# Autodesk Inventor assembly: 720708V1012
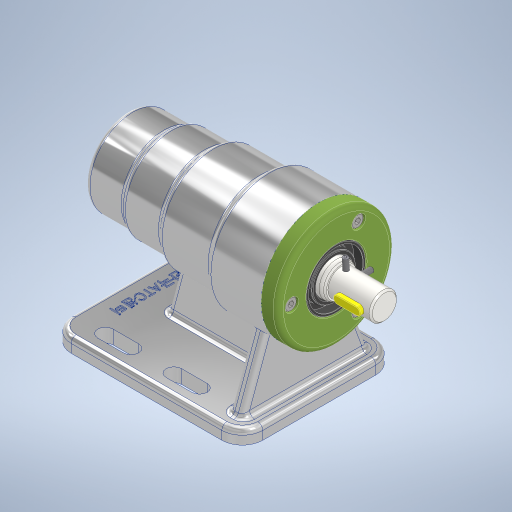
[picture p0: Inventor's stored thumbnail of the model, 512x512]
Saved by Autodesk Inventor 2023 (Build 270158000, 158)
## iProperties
Created: 2022-07
Part Number: 720708V1012
Document SubType Name: Assembly
Designer: owner
Author: owner
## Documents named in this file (12)
- C:\Users\owner\Desktop\720708V1012\720708V1012.iam
- C:\Users\owner\Desktop\720708V1012\본체.ipt
- C:\Users\owner\Desktop\720708V1012\V벨트풀리.ipt
- C:\Users\owner\Desktop\720708V1012\멈춤나사 M3.ipt
- C:\Users\owner\Desktop\720708V1012\베어링 6004.ipt
- C:\Users\owner\Desktop\720708V1012\베어링 51202.ipt
- C:\Users\owner\Desktop\720708V1012\볼트 M4.ipt
- C:\Users\owner\Desktop\720708V1012\어댑터슬리브.ipt
- C:\Users\owner\Desktop\720708V1012\오일 실 20x35x7.ipt
- C:\Users\owner\Desktop\720708V1012\축.ipt
- C:\Users\owner\Desktop\720708V1012\커버.ipt
- C:\Users\owner\Desktop\720708V1012\키 5x5.ipt
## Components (1 placed, 1 different names)
1. V벨트풀리:1
